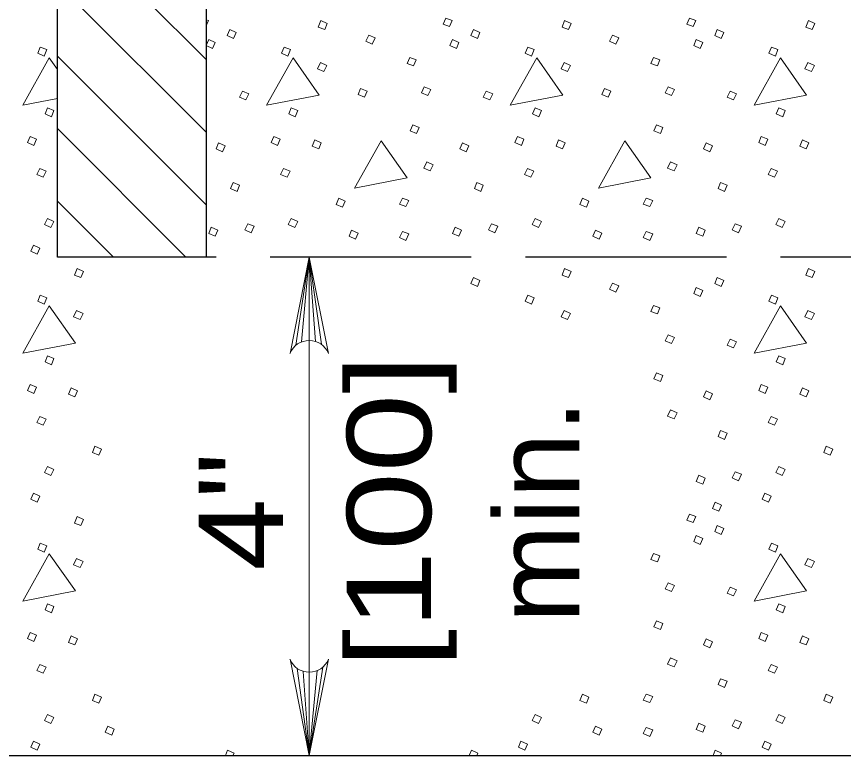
# Model space of a CAD drawing. Extents: x 1083.1 to 1117.1, y 719.4 to 741.4.
# Drawn here: x 1100.521 to 1102.051, y 722.701 to 724.068 of the extents above; entities that cross this region are included whole.
import ezdxf
from ezdxf.enums import TextEntityAlignment as Align

# ---------------------------------------------------------------- set-up
doc = ezdxf.new("R2010")
doc.units = 0
doc.header["$LTSCALE"] = 0.062
doc.linetypes.add('LONG_DASHED', pattern=[7.5, 6, -1.5])
doc.layers.add('1', color=7, linetype='Continuous', lineweight=13)

msp = doc.modelspace()

# ---------------------------------------------------------------- linework, layer by layer
at = {"layer": '1', "lineweight": 25}
msp.add_line((1100.59642, 723.623), (1100.59642, 725.51267), dxfattribs=at)
at = {"layer": '1'}
for p, q in [((1100.59642, 724.26367), (1100.8715, 723.9885)), ((1100.59642, 724.12933), (1100.8715, 723.85425)), ((1100.59642, 723.97042), (1100.58125, 723.99192)), ((1100.59642, 723.99508), (1100.8715, 723.72)), ((1100.59642, 723.86083), (1100.83425, 723.623)), ((1100.59642, 723.72658), (1100.7, 723.623)), ((1101.03742, 723.45992), (1101.06233, 723.623)), ((1101.04783, 723.46608), (1101.06233, 723.623)), ((1101.06233, 723.623), (1101.06233, 722.701)), ((1101.06233, 723.46892), (1101.06233, 723.623)), ((1101.07375, 723.46725), (1101.06233, 723.623)), ((1101.08483, 723.46183), (1101.06233, 723.623)), ((1101.03975, 722.86217), (1101.06233, 722.701)), ((1101.05092, 722.85667), (1101.06233, 722.701)), ((1101.08725, 722.86408), (1101.06233, 722.701)), ((1101.07683, 722.85792), (1101.06233, 722.701)), ((1101.06233, 722.85508), (1101.06233, 722.701)), ((1100.90733, 722.701), (1100.91125, 722.711)), ((1101.35833, 722.701), (1101.36233, 722.711)), ((1101.80942, 722.701), (1101.81333, 722.711))]:
    msp.add_line(p, q, dxfattribs=at)
at = {"layer": '1', "linetype": 'LONG_DASHED', "lineweight": 25}
msp.add_line((1103.25025, 723.623), (1100.8715, 723.623), dxfattribs=at)
at = {"layer": '1', "lineweight": 25}
for points in [[(1099.65058, 725.51267), (1099.65058, 722.701), (1104.49067, 722.701)], [(1100.8715, 725.51267), (1100.8715, 723.623), (1100.59642, 723.623)]]:
    msp.add_lwpolyline(points, dxfattribs=at)
at = {"layer": '1'}
for points in [[(1101.31483, 724.0655), (1101.32667, 724.06075), (1101.32192, 724.04967), (1101.31008, 724.05442)], [(1101.76583, 724.0655), (1101.77775, 724.06075), (1101.773, 724.04967), (1101.76108, 724.05442)], [(1101.08375, 724.06075), (1101.09567, 724.05525), (1101.09092, 724.04417), (1101.079, 724.04892)], [(1101.53483, 724.06075), (1101.54667, 724.05525), (1101.54192, 724.04417), (1101.53008, 724.04892)], [(1101.98583, 724.06075), (1101.99767, 724.05525), (1101.993, 724.04417), (1101.98108, 724.04892)], [(1100.91525, 724.04417), (1100.92708, 724.03858), (1100.92233, 724.0275), (1100.9105, 724.03308)], [(1101.17242, 724.03383), (1101.18425, 724.02908), (1101.17875, 724.01725), (1101.16683, 724.02283)], [(1101.36625, 724.04417), (1101.37808, 724.03858), (1101.37342, 724.0275), (1101.3615, 724.03308)], [(1101.62342, 724.03383), (1101.63533, 724.02908), (1101.62975, 724.01725), (1101.61792, 724.02283)], [(1101.81725, 724.04417), (1101.82917, 724.03858), (1101.82442, 724.0275), (1101.81258, 724.03308)], [(1100.87642, 724.02592), (1100.88833, 724.02042), (1100.88358, 724.00933), (1100.87167, 724.01492)], [(1101.3275, 724.02592), (1101.33933, 724.02042), (1101.33458, 724.00933), (1101.32275, 724.01492)], [(1101.7785, 724.02592), (1101.79042, 724.02042), (1101.78567, 724.00933), (1101.77375, 724.01492)], [(1100.56467, 724.01175), (1100.57658, 724.007), (1100.57183, 723.99508), (1100.55992, 724.00067)], [(1101.01575, 724.01175), (1101.02758, 724.007), (1101.02283, 723.99508), (1101.011, 724.00067)], [(1101.46675, 724.01175), (1101.47858, 724.007), (1101.47383, 723.99508), (1101.462, 724.00067)], [(1101.91775, 724.01175), (1101.92967, 724.007), (1101.92492, 723.99508), (1101.913, 724.00067)], [(1101.03233, 723.99192), (1100.98325, 723.90408), (1101.08058, 723.92308)], [(1101.24833, 723.99275), (1101.26025, 723.988), (1101.2555, 723.97692), (1101.24358, 723.98167)], [(1101.48333, 723.99192), (1101.43433, 723.90408), (1101.53167, 723.92308)], [(1101.69942, 723.99275), (1101.71125, 723.988), (1101.7065, 723.97692), (1101.69467, 723.98167)], [(1101.93442, 723.99192), (1101.88533, 723.90408), (1101.98267, 723.92308)], [(1101.083, 723.98325), (1101.09483, 723.97767), (1101.08933, 723.96658), (1101.07742, 723.97133)], [(1101.534, 723.98325), (1101.54592, 723.97767), (1101.54033, 723.96658), (1101.5285, 723.97133)], [(1101.98508, 723.98325), (1101.99692, 723.97767), (1101.99142, 723.96658), (1101.9795, 723.97133)], [(1100.93892, 723.93025), (1100.95083, 723.9255), (1100.94525, 723.91442), (1100.93342, 723.91917)], [(1101.15733, 723.935), (1101.16925, 723.93025), (1101.1645, 723.91917), (1101.15258, 723.92392)], [(1101.27525, 723.93817), (1101.28717, 723.93342), (1101.28158, 723.92233), (1101.26975, 723.92708)], [(1101.39, 723.93025), (1101.40183, 723.9255), (1101.39633, 723.91442), (1101.38442, 723.91917)], [(1101.60842, 723.935), (1101.62025, 723.93025), (1101.6155, 723.91917), (1101.60367, 723.92392)], [(1101.72633, 723.93817), (1101.73817, 723.93342), (1101.73258, 723.92233), (1101.72075, 723.92708)], [(1101.841, 723.93025), (1101.85292, 723.9255), (1101.84733, 723.91442), (1101.8355, 723.91917)], [(1100.57817, 723.89933), (1100.59, 723.89458), (1100.58525, 723.88275), (1100.57342, 723.88825)], [(1101.02917, 723.89933), (1101.041, 723.89458), (1101.03625, 723.88275), (1101.02442, 723.88825)], [(1101.48017, 723.89933), (1101.49208, 723.89458), (1101.48733, 723.88275), (1101.47542, 723.88825)], [(1101.93125, 723.89933), (1101.94308, 723.89458), (1101.93833, 723.88275), (1101.9265, 723.88825)], [(1101.25392, 723.86775), (1101.26575, 723.863), (1101.261, 723.85192), (1101.24917, 723.85667)], [(1101.70492, 723.86775), (1101.71683, 723.863), (1101.71208, 723.85192), (1101.70017, 723.85667)], [(1100.54567, 723.84633), (1100.55758, 723.84158), (1100.55283, 723.82975), (1100.54092, 723.83525)], [(1100.89467, 723.8345), (1100.9065, 723.82892), (1100.90175, 723.81783), (1100.88992, 723.82342)], [(1100.99675, 723.84633), (1101.00858, 723.84158), (1101.00383, 723.82975), (1100.992, 723.83525)], [(1101.07267, 723.84), (1101.08458, 723.8345), (1101.07983, 723.82342), (1101.06792, 723.82817)], [(1101.19533, 723.83842), (1101.14625, 723.75058), (1101.24358, 723.76958)], [(1101.34567, 723.8345), (1101.35758, 723.82892), (1101.35283, 723.81783), (1101.34092, 723.82342)], [(1101.44775, 723.84633), (1101.45967, 723.84158), (1101.45492, 723.82975), (1101.443, 723.83525)], [(1101.52375, 723.84), (1101.53558, 723.8345), (1101.53083, 723.82342), (1101.519, 723.82817)], [(1101.64642, 723.83842), (1101.59733, 723.75058), (1101.69467, 723.76958)], [(1101.79675, 723.8345), (1101.80858, 723.82892), (1101.80383, 723.81783), (1101.792, 723.82342)], [(1101.89883, 723.84633), (1101.91067, 723.84158), (1101.90592, 723.82975), (1101.89408, 723.83525)], [(1101.97475, 723.84), (1101.98667, 723.8345), (1101.98192, 723.82342), (1101.97, 723.82817)], [(1101.28, 723.79967), (1101.29183, 723.79417), (1101.28633, 723.78308), (1101.2745, 723.78783)], [(1101.731, 723.79967), (1101.74292, 723.79417), (1101.73733, 723.78308), (1101.7255, 723.78783)], [(1100.56392, 723.787), (1100.57575, 723.78225), (1100.57025, 723.77117), (1100.55833, 723.77592)], [(1101.01492, 723.787), (1101.02675, 723.78225), (1101.02125, 723.77117), (1101.00942, 723.77592)], [(1101.46592, 723.787), (1101.47783, 723.78225), (1101.47225, 723.77117), (1101.46042, 723.77592)], [(1101.917, 723.787), (1101.92883, 723.78225), (1101.92333, 723.77117), (1101.91142, 723.77592)], [(1100.92158, 723.76092), (1100.93342, 723.75617), (1100.92867, 723.74425), (1100.91683, 723.74983)], [(1101.37258, 723.76092), (1101.38442, 723.75617), (1101.37967, 723.74425), (1101.36783, 723.74983)], [(1101.82358, 723.76092), (1101.8355, 723.75617), (1101.83075, 723.74425), (1101.81883, 723.74983)], [(1101.117, 723.73242), (1101.12883, 723.72692), (1101.12408, 723.71583), (1101.11225, 723.72058)], [(1101.23492, 723.73242), (1101.24675, 723.72767), (1101.24125, 723.71658), (1101.22933, 723.72133)], [(1101.568, 723.73242), (1101.57992, 723.72692), (1101.57517, 723.71583), (1101.56325, 723.72058)], [(1101.68592, 723.73242), (1101.69783, 723.72767), (1101.69225, 723.71658), (1101.68042, 723.72133)], [(1100.57817, 723.69442), (1100.59, 723.68892), (1100.58442, 723.67783), (1100.57258, 723.68333)], [(1100.94842, 723.68492), (1100.96033, 723.68017), (1100.95475, 723.66833), (1100.94292, 723.67383)], [(1101.02917, 723.69442), (1101.041, 723.68892), (1101.0355, 723.67783), (1101.02358, 723.68333)], [(1101.3995, 723.68492), (1101.41133, 723.68017), (1101.40583, 723.66833), (1101.39392, 723.67383)], [(1101.48017, 723.69442), (1101.49208, 723.68892), (1101.4865, 723.67783), (1101.47467, 723.68333)], [(1101.8505, 723.68492), (1101.86242, 723.68017), (1101.85683, 723.66833), (1101.845, 723.67383)], [(1101.93125, 723.69442), (1101.94308, 723.68892), (1101.93758, 723.67783), (1101.92567, 723.68333)], [(1100.88117, 723.67858), (1100.89308, 723.67308), (1100.88833, 723.662), (1100.87642, 723.66675)], [(1101.14075, 723.67308), (1101.15258, 723.6675), (1101.14783, 723.6565), (1101.136, 723.662)], [(1101.23492, 723.67067), (1101.24675, 723.66592), (1101.24125, 723.65408), (1101.22933, 723.65967)], [(1101.33225, 723.67858), (1101.34408, 723.67308), (1101.33933, 723.662), (1101.3275, 723.66675)], [(1101.59175, 723.67308), (1101.60367, 723.6675), (1101.59892, 723.6565), (1101.587, 723.662)], [(1101.68592, 723.67067), (1101.69783, 723.66592), (1101.69225, 723.65408), (1101.68042, 723.65967)], [(1101.78325, 723.67858), (1101.79517, 723.67308), (1101.79042, 723.662), (1101.7785, 723.66675)], [(1100.552, 723.64542), (1100.56392, 723.63983), (1100.55917, 723.62875), (1100.54725, 723.63433)], [(1100.63275, 723.60183), (1100.64458, 723.59633), (1100.63983, 723.58525), (1100.628, 723.59)], [(1101.53483, 723.60183), (1101.54667, 723.59633), (1101.54192, 723.58525), (1101.53008, 723.59)], [(1101.98583, 723.60183), (1101.99767, 723.59633), (1101.993, 723.58525), (1101.98108, 723.59)], [(1101.36625, 723.58525), (1101.37808, 723.57975), (1101.37342, 723.56867), (1101.3615, 723.57417)], [(1101.62342, 723.575), (1101.63533, 723.57025), (1101.62975, 723.55833), (1101.61792, 723.56392)], [(1101.81725, 723.58525), (1101.82917, 723.57975), (1101.82442, 723.56867), (1101.81258, 723.57417)], [(1101.7785, 723.56708), (1101.79042, 723.5615), (1101.78567, 723.55042), (1101.77375, 723.556)], [(1100.56467, 723.55283), (1100.57658, 723.54808), (1100.57183, 723.53617), (1100.55992, 723.54175)], [(1101.46675, 723.55283), (1101.47858, 723.54808), (1101.47383, 723.53617), (1101.462, 723.54175)], [(1101.91775, 723.55283), (1101.92967, 723.54808), (1101.92492, 723.53617), (1101.913, 723.54175)], [(1100.58125, 723.533), (1100.53225, 723.44517), (1100.62958, 723.46417)], [(1101.69942, 723.53383), (1101.71125, 723.52908), (1101.7065, 723.518), (1101.69467, 723.52275)], [(1101.93442, 723.533), (1101.88533, 723.44517), (1101.98267, 723.46417)], [(1100.63192, 723.52433), (1100.64383, 723.51875), (1100.63825, 723.50775), (1100.62642, 723.51242)], [(1101.534, 723.52433), (1101.54592, 723.51875), (1101.54033, 723.50775), (1101.5285, 723.51242)], [(1101.98508, 723.52433), (1101.99692, 723.51875), (1101.99142, 723.50775), (1101.9795, 723.51242)], [(1101.72633, 723.47925), (1101.73817, 723.4745), (1101.73258, 723.46342), (1101.72075, 723.46817)], [(1101.841, 723.47133), (1101.85292, 723.46658), (1101.84733, 723.4555), (1101.8355, 723.46025)], [(1100.57817, 723.4405), (1100.59, 723.43575), (1100.58525, 723.42383), (1100.57342, 723.42942)], [(1101.93125, 723.4405), (1101.94308, 723.43575), (1101.93833, 723.42383), (1101.9265, 723.42942)], [(1101.70492, 723.40883), (1101.71683, 723.40408), (1101.71208, 723.393), (1101.70017, 723.39775)], [(1100.54567, 723.38742), (1100.55758, 723.38267), (1100.55283, 723.37083), (1100.54092, 723.37633)], [(1100.62167, 723.38108), (1100.6335, 723.37558), (1100.62875, 723.3645), (1100.61692, 723.36925)], [(1101.79675, 723.37558), (1101.80858, 723.37008), (1101.80383, 723.359), (1101.792, 723.3645)], [(1101.89883, 723.38742), (1101.91067, 723.38267), (1101.90592, 723.37083), (1101.89408, 723.37633)], [(1101.97475, 723.38108), (1101.98667, 723.37558), (1101.98192, 723.3645), (1101.97, 723.36925)], [(1101.731, 723.34075), (1101.74292, 723.33525), (1101.73733, 723.32417), (1101.7255, 723.32892)], [(1100.56392, 723.32808), (1100.57575, 723.32333), (1100.57025, 723.31225), (1100.55833, 723.317)], [(1101.917, 723.32808), (1101.92883, 723.32333), (1101.92333, 723.31225), (1101.91142, 723.317)], [(1101.82358, 723.302), (1101.8355, 723.29725), (1101.83075, 723.28542), (1101.81883, 723.29092)], [(1100.66592, 723.2735), (1100.67783, 723.268), (1100.67308, 723.25692), (1100.66125, 723.26167)], [(1102.01908, 723.2735), (1102.03092, 723.268), (1102.02617, 723.25692), (1102.01433, 723.26167)], [(1100.57817, 723.2355), (1100.59, 723.23), (1100.58442, 723.21892), (1100.57258, 723.2245)], [(1101.8505, 723.22608), (1101.86242, 723.22133), (1101.85683, 723.20942), (1101.845, 723.215)], [(1101.93125, 723.2355), (1101.94308, 723.23), (1101.93758, 723.21892), (1101.92567, 723.2245)], [(1101.78325, 723.21975), (1101.79517, 723.21417), (1101.79042, 723.20308), (1101.7785, 723.20783)], [(1100.552, 723.1865), (1100.56392, 723.18092), (1100.55917, 723.16983), (1100.54725, 723.17542)], [(1101.90517, 723.1865), (1101.917, 723.18092), (1101.91225, 723.16983), (1101.90042, 723.17542)], [(1101.81333, 723.16983), (1101.82517, 723.16433), (1101.82042, 723.15325), (1101.80858, 723.158)], [(1101.76583, 723.14775), (1101.77775, 723.143), (1101.773, 723.13192), (1101.76108, 723.13667)], [(1100.63275, 723.143), (1100.64458, 723.13742), (1100.63983, 723.12633), (1100.628, 723.13108)], [(1101.81725, 723.12633), (1101.82917, 723.12083), (1101.82442, 723.10975), (1101.81258, 723.11525)], [(1101.7785, 723.10817), (1101.79042, 723.10258), (1101.78567, 723.0915), (1101.77375, 723.09708)], [(1100.56467, 723.09392), (1100.57658, 723.08917), (1100.57183, 723.07733), (1100.55992, 723.08283)], [(1101.91775, 723.09392), (1101.92967, 723.08917), (1101.92492, 723.07733), (1101.913, 723.08283)], [(1100.58125, 723.07417), (1100.53225, 722.98633), (1100.62958, 723.00533)], [(1101.69942, 723.07492), (1101.71125, 723.07017), (1101.7065, 723.05908), (1101.69467, 723.06383)], [(1101.93442, 723.07417), (1101.88533, 722.98633), (1101.98267, 723.00533)], [(1100.63192, 723.06542), (1100.64383, 723.05992), (1100.63825, 723.04883), (1100.62642, 723.05358)], [(1101.98508, 723.06542), (1101.99692, 723.05992), (1101.99142, 723.04883), (1101.9795, 723.05358)], [(1101.72633, 723.02033), (1101.73817, 723.01558), (1101.73258, 723.0045), (1101.72075, 723.00925)], [(1101.841, 723.01242), (1101.85292, 723.00767), (1101.84733, 722.99658), (1101.8355, 723.00133)], [(1100.57817, 722.98158), (1100.59, 722.97683), (1100.58525, 722.96492), (1100.57342, 722.9705)], [(1101.93125, 722.98158), (1101.94308, 722.97683), (1101.93833, 722.96492), (1101.9265, 722.9705)], [(1101.70492, 722.94992), (1101.71683, 722.94517), (1101.71208, 722.93408), (1101.70017, 722.93883)], [(1100.54567, 722.92858), (1100.55758, 722.92383), (1100.55283, 722.91192), (1100.54092, 722.9175)], [(1100.62167, 722.92225), (1100.6335, 722.91667), (1100.62875, 722.90558), (1100.61692, 722.91033)], [(1101.79675, 722.91667), (1101.80858, 722.91117), (1101.80383, 722.90008), (1101.792, 722.90558)], [(1101.89883, 722.92858), (1101.91067, 722.92383), (1101.90592, 722.91192), (1101.89408, 722.9175)], [(1101.97475, 722.92225), (1101.98667, 722.91667), (1101.98192, 722.90558), (1101.97, 722.91033)], [(1101.731, 722.88183), (1101.74292, 722.87633), (1101.73733, 722.86525), (1101.7255, 722.87)], [(1100.56392, 722.86917), (1100.57575, 722.86442), (1100.57025, 722.85342), (1100.55833, 722.85817)], [(1101.917, 722.86917), (1101.92883, 722.86442), (1101.92333, 722.85342), (1101.91142, 722.85817)], [(1101.82358, 722.84308), (1101.8355, 722.83833), (1101.83075, 722.8265), (1101.81883, 722.832)], [(1100.66592, 722.81458), (1100.67783, 722.80908), (1100.67308, 722.798), (1100.66125, 722.80275)], [(1101.568, 722.81458), (1101.57992, 722.80908), (1101.57517, 722.798), (1101.56325, 722.80275)], [(1101.68592, 722.81458), (1101.69783, 722.80983), (1101.69225, 722.79875), (1101.68042, 722.8035)], [(1102.01908, 722.81458), (1102.03092, 722.80908), (1102.02617, 722.798), (1102.01433, 722.80275)], [(1100.57817, 722.77667), (1100.59, 722.77108), (1100.58442, 722.76), (1100.57258, 722.76558)], [(1101.48017, 722.77667), (1101.49208, 722.77108), (1101.4865, 722.76), (1101.47467, 722.76558)], [(1101.8505, 722.76717), (1101.86242, 722.76242), (1101.85683, 722.7505), (1101.845, 722.75608)], [(1101.93125, 722.77667), (1101.94308, 722.77108), (1101.93758, 722.76), (1101.92567, 722.76558)], [(1100.68967, 722.75525), (1100.70158, 722.74975), (1100.69683, 722.73867), (1100.68492, 722.74417)], [(1101.59175, 722.75525), (1101.60367, 722.74975), (1101.59892, 722.73867), (1101.587, 722.74417)], [(1101.68592, 722.75292), (1101.69783, 722.74817), (1101.69225, 722.73625), (1101.68042, 722.74183)], [(1101.78325, 722.76083), (1101.79517, 722.75525), (1101.79042, 722.74417), (1101.7785, 722.74892)], [(1100.552, 722.72758), (1100.56392, 722.72208), (1100.55917, 722.711), (1100.54725, 722.7165)], [(1101.45408, 722.72758), (1101.46592, 722.72208), (1101.46125, 722.711), (1101.44933, 722.7165)], [(1101.90517, 722.72758), (1101.917, 722.72208), (1101.91225, 722.711), (1101.90042, 722.7165)]]:
    msp.add_lwpolyline(points, close=True, dxfattribs=at)
for points in [[(1100.8715, 724.06242), (1100.87567, 724.06075), (1100.8715, 724.05117)], [(1100.58125, 723.99192), (1100.53225, 723.90408), (1100.59642, 723.91658)], [(1101.02675, 723.445), (1101.06233, 723.623), (1101.09792, 723.445)], [(1101.09792, 722.879), (1101.06233, 722.701), (1101.02675, 722.879)], [(1100.91125, 722.711), (1100.92317, 722.70542), (1100.92125, 722.701)], [(1101.36233, 722.711), (1101.37417, 722.70542), (1101.37225, 722.701)], [(1101.81333, 722.711), (1101.82517, 722.70542), (1101.82333, 722.701)]]:
    msp.add_lwpolyline(points, dxfattribs=at)
for centre, major_axis in [((1101.06232, 723.43052), (0.03843, 0)), ((1101.06232, 722.89347), (-0.03843, 0))]:
    msp.add_ellipse(centre, major_axis=major_axis, ratio=0.999895, start_param=0.3855052, end_param=2.7561184, dxfattribs=at)

# ---------------------------------------------------------------- texts
for s, width, p in [('[100]', 1.25, (1101.28783, 723.1525)), ('min.', 1.05, (1101.56183, 723.1525)), ('4"', 1.15, (1101.01383, 723.1525))]:
    msp.add_text(s, height=0.156, rotation=90, dxfattribs=dict(at, width=width)).set_placement(p, align=Align.CENTER)

doc.saveas('drawing.dxf')
